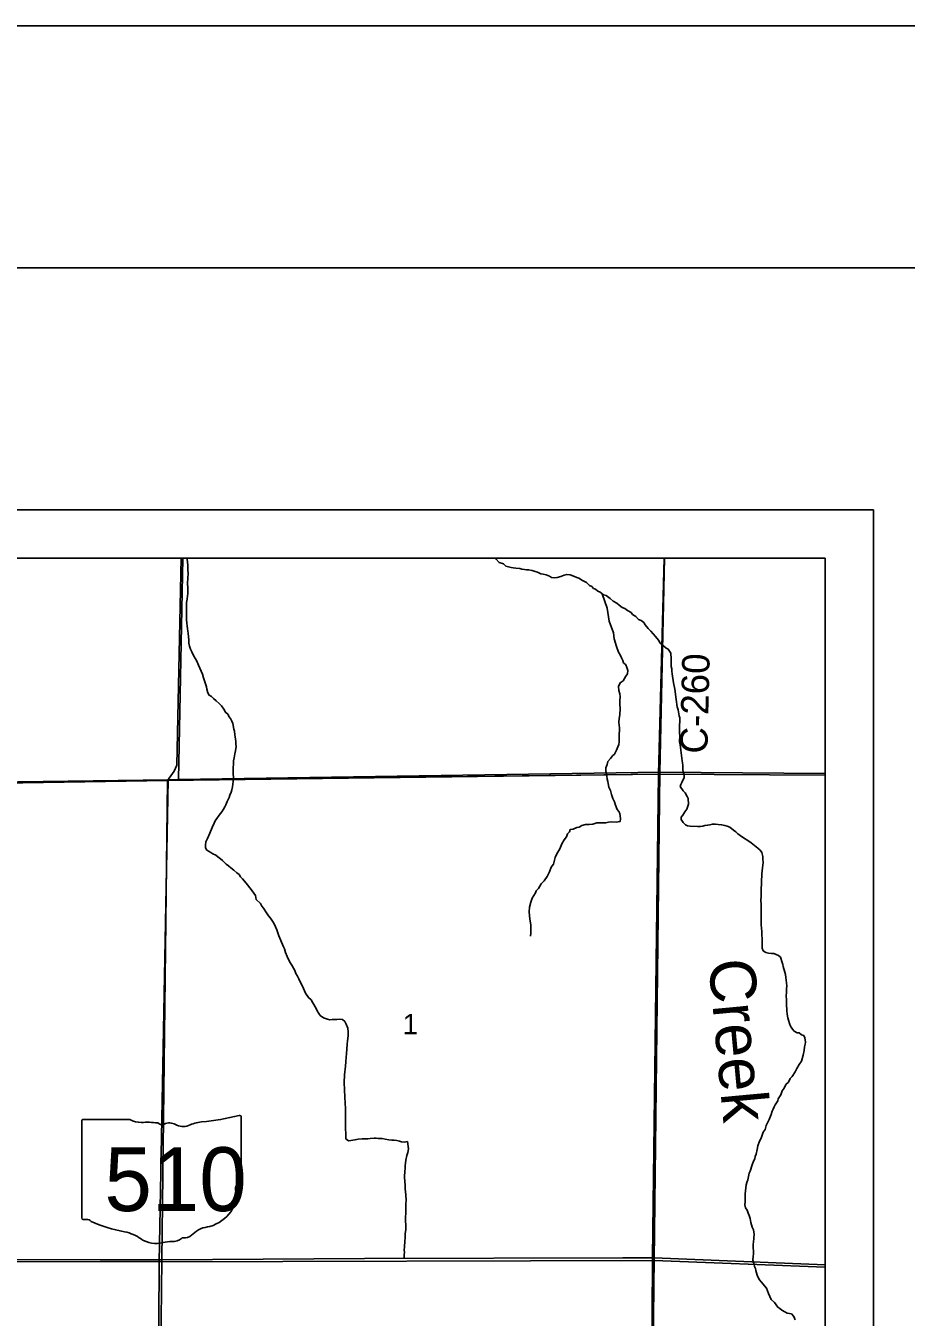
# Model space of a CAD drawing. Extents: x 0 to 34, y 0 to 22.
# Drawn here: x 7.249 to 9.068, y 19.332 to 22 of the extents above; entities that cross this region are included whole.
import ezdxf

# ---------------------------------------------------------------- set-up
doc = ezdxf.new("R2010")
doc.units = 0
for name, color, linetype in [('Default', 7, 'Continuous'), ('GM_X_County_Road', 7, 'Continuous'), ('GM_X_County_Road_Text', 7, 'Continuous'), ('GM_X_Minor_River', 7, 'Continuous'), ('GM_X_Minor_River_Text', 7, 'Continuous'), ('GM_X_Section', 7, 'Continuous'), ('GM_X_Section_Text', 7, 'Continuous'), ('GM_X_State_Location', 7, 'Continuous'), ('GM_X_State_Route', 7, 'Continuous'), ('GM_X_State_Shield', 7, 'Continuous'), ('GM_X_Township', 7, 'Continuous'), ('GM_X_Township_Road', 7, 'Continuous'), ('SH_Border', 7, 'Continuous'), ('SH_Cut_Line', 7, 'Continuous'), ('SH_Data', 7, 'Continuous')]:
    doc.layers.add(name, color=color, linetype=linetype)

msp = doc.modelspace()

# ---------------------------------------------------------------- linework, layer by layer
at = {"layer": 'Default'}
for points in [[(7.573, 20.9), (6.5742, 20.9), (6.5611, 20.4294), (7.5428, 20.4426), (7.5641, 20.4428)], [(8.5686, 20.9), (7.573, 20.9), (7.5641, 20.4428), (8.5583, 20.4582)], [(8.9, 20.4555), (8.9, 20.9), (8.5686, 20.9), (8.5583, 20.4582)], [(8.9, 19.4359), (8.9, 20.4555), (8.5583, 20.4582), (8.547, 19.4493)], [(8.9, 18.4355), (8.9, 19.4359), (8.547, 19.4493), (8.532, 18.4506)]]:
    msp.add_lwpolyline(points, close=True, dxfattribs=at)
at = {"layer": 'GM_X_County_Road'}
msp.add_line((8.5562, 20.4539), (8.5678, 20.9), dxfattribs=at)
msp.add_lwpolyline([(6.5577, 20.4253), (7.5411, 20.4409), (8.5562, 20.4539)], dxfattribs=at)
at = {"layer": 'GM_X_Minor_River'}
for points in [[(7.5819, 20.9), (7.582, 20.8985), (7.5824, 20.8917), (7.5832, 20.886), (7.5836, 20.878), (7.5837, 20.8666), (7.5833, 20.8609), (7.583, 20.8564), (7.5826, 20.851)], [(8.2191, 20.9), (8.2205, 20.8985), (8.2266, 20.8913), (8.2353, 20.8883), (8.2407, 20.8838), (8.2456, 20.8827), (8.2513, 20.8812), (8.2559, 20.8801), (8.2612, 20.8793), (8.2696, 20.879), (8.2737, 20.8779), (8.2787, 20.8772), (8.2829, 20.8764), (8.2874, 20.8764), (8.2946, 20.8749), (8.3011, 20.8727), (8.3057, 20.8712), (8.3129, 20.8682), (8.3174, 20.8675), (8.3239, 20.866), (8.3307, 20.863), (8.3349, 20.8607), (8.341, 20.8596), (8.3463, 20.8604), (8.3543, 20.8627), (8.3611, 20.8654), (8.3664, 20.8669), (8.3732, 20.8658), (8.3786, 20.864), (8.3869, 20.8606), (8.3915, 20.8587), (8.3991, 20.8542), (8.4071, 20.8497), (8.4136, 20.844), (8.4178, 20.8421), (8.4216, 20.8379), (8.4258, 20.8364), (8.4307, 20.8319), (8.4353, 20.83), (8.4425, 20.8248), (8.4475, 20.8229), (8.4559, 20.8172), (8.4623, 20.8116), (8.47, 20.8074), (8.4749, 20.8033), (8.4806, 20.7983), (8.4863, 20.7961), (8.4921, 20.7923), (8.4993, 20.7878), (8.5023, 20.7836), (8.5092, 20.7799), (8.5149, 20.7738), (8.5202, 20.7716), (8.5256, 20.7674), (8.5283, 20.7625), (8.5348, 20.7549), (8.5401, 20.7492), (8.5447, 20.7443), (8.5496, 20.7387), (8.5561, 20.7307), (8.5596, 20.725), (8.5664, 20.7194), (8.5718, 20.7141), (8.576, 20.7122), (8.5817, 20.7042), (8.5818, 20.6921), (8.5818, 20.6852), (8.5822, 20.6765), (8.5834, 20.672), (8.5834, 20.667), (8.5842, 20.6613), (8.5866, 20.6431), (8.5893, 20.6298)], [(7.5826, 20.851), (7.5831, 20.8366), (7.5831, 20.8263), (7.5828, 20.8222), (7.5817, 20.8153), (7.5809, 20.8085), (7.5806, 20.8009), (7.5806, 20.7959), (7.5803, 20.7887), (7.5803, 20.7796), (7.5807, 20.7728), (7.5811, 20.7667), (7.5819, 20.7595), (7.5827, 20.7549), (7.5835, 20.7492), (7.5839, 20.7451), (7.5847, 20.7378), (7.5851, 20.7318), (7.5855, 20.7245), (7.5867, 20.7185), (7.5886, 20.7124), (7.5913, 20.7071), (7.5955, 20.6976), (7.5994, 20.6923), (7.6017, 20.6874), (7.6055, 20.6791), (7.6078, 20.6734), (7.6136, 20.6605), (7.6155, 20.6529), (7.6186, 20.6446), (7.6205, 20.6389), (7.6217, 20.6343), (7.6228, 20.6294), (7.6248, 20.6222), (7.6271, 20.6172), (7.632, 20.6142), (7.6366, 20.6101), (7.6419, 20.6055), (7.648, 20.6002), (7.6526, 20.595), (7.6576, 20.5885), (7.661, 20.5821), (7.6664, 20.5775), (7.6683, 20.5734), (7.6717, 20.5692), (7.674, 20.5639), (7.676, 20.559), (7.6787, 20.5468), (7.6794, 20.5427), (7.6806, 20.5354), (7.6814, 20.5313), (7.6822, 20.5214), (7.6826, 20.5161), (7.683, 20.5111), (7.6819, 20.502), (7.6804, 20.4959), (7.679, 20.4876), (7.6779, 20.4815), (7.6779, 20.4762), (7.6772, 20.4663), (7.6772, 20.4534), (7.6776, 20.4484), (7.6773, 20.4386), (7.6766, 20.4332), (7.6755, 20.4279), (7.674, 20.4215), (7.6729, 20.4169), (7.6702, 20.4108), (7.6684, 20.4062), (7.6669, 20.4017), (7.6646, 20.3975), (7.662, 20.391), (7.6597, 20.3864), (7.6567, 20.3819), (7.6537, 20.3765), (7.6484, 20.3693), (7.6432, 20.3624), (7.6398, 20.3575), (7.6375, 20.3529), (7.6334, 20.3438), (7.6285, 20.332), (7.624, 20.3209), (7.6202, 20.3141), (7.6195, 20.3072), (7.6195, 20.3023), (7.6218, 20.2977), (7.626, 20.2951), (7.6306, 20.2925), (7.6348, 20.2898), (7.6409, 20.2868), (7.6451, 20.283), (7.6508, 20.2793), (7.655, 20.2755), (7.6626, 20.2683), (7.6672, 20.2645), (7.6721, 20.2604), (7.6782, 20.2555), (7.6847, 20.2502), (7.6893, 20.2468), (7.692, 20.2422), (7.6965, 20.2381)], [(8.4396, 20.8269), (8.4499, 20.7971), (8.4542, 20.7701), (8.4631, 20.7462), (8.4643, 20.7337), (8.4693, 20.7181), (8.4731, 20.7064), (8.4769, 20.7007), (8.4796, 20.6943), (8.4823, 20.6886), (8.4839, 20.6844), (8.4884, 20.6802), (8.4904, 20.6742), (8.4927, 20.6685), (8.4919, 20.6613), (8.4882, 20.6567), (8.4829, 20.6472), (8.4769, 20.643), (8.4731, 20.6353), (8.4739, 20.6266), (8.4758, 20.6202), (8.477, 20.6148), (8.4763, 20.6057), (8.4763, 20.5989), (8.4767, 20.5898), (8.4761, 20.5769), (8.4746, 20.5689), (8.4739, 20.5616), (8.4746, 20.5544), (8.475, 20.5503), (8.4755, 20.5442), (8.4747, 20.537), (8.4744, 20.5309), (8.4744, 20.5206), (8.4737, 20.5153), (8.4722, 20.5104), (8.4688, 20.5039), (8.4651, 20.4955), (8.4605, 20.4917), (8.4568, 20.4867), (8.4515, 20.4806), (8.4496, 20.4738), (8.447, 20.4669), (8.447, 20.4597), (8.4486, 20.4548), (8.4494, 20.4506), (8.4501, 20.4438), (8.4513, 20.4388), (8.4521, 20.4347), (8.4536, 20.4271), (8.4567, 20.4203), (8.4587, 20.4123), (8.4614, 20.4036), (8.4648, 20.3971), (8.4671, 20.3899), (8.4706, 20.3812), (8.474, 20.3767), (8.4759, 20.3725), (8.4767, 20.3679), (8.4775, 20.3615), (8.4768, 20.3565), (8.4684, 20.355), (8.4597, 20.3553), (8.4529, 20.3549), (8.4468, 20.3537), (8.4388, 20.3533), (8.4282, 20.3533), (8.424, 20.3525), (8.4199, 20.3509), (8.4127, 20.3501), (8.4051, 20.3501), (8.3975, 20.3478), (8.3918, 20.3447), (8.3873, 20.3436), (8.3797, 20.3405), (8.3736, 20.3397), (8.3717, 20.3348), (8.368, 20.3306), (8.3661, 20.3245), (8.3612, 20.3184), (8.3563, 20.31), (8.3518, 20.2997), (8.3458, 20.2898), (8.3424, 20.2818), (8.339, 20.2685), (8.3341, 20.262), (8.3308, 20.2525), (8.3259, 20.2426), (8.3195, 20.2335), (8.3131, 20.2277), (8.3104, 20.2228), (8.3078, 20.2182), (8.3033, 20.2133), (8.3014, 20.2091), (8.2984, 20.2037), (8.2946, 20.198), (8.292, 20.19), (8.2894, 20.1794), (8.2883, 20.1695), (8.2891, 20.1623), (8.2899, 20.1547)], [(8.5893, 20.6298), (8.5912, 20.6196), (8.592, 20.6131), (8.5924, 20.6082), (8.5948, 20.593), (8.5967, 20.5869), (8.5987, 20.5748), (8.5998, 20.5706), (8.6002, 20.5653), (8.5995, 20.5528), (8.5992, 20.5474), (8.5992, 20.5417), (8.5997, 20.5307), (8.5993, 20.525), (8.5993, 20.5205), (8.6005, 20.5148), (8.6013, 20.5098), (8.6017, 20.5038), (8.6025, 20.4981), (8.604, 20.4874), (8.6045, 20.4814), (8.6052, 20.4772), (8.606, 20.4723), (8.6064, 20.4677), (8.6064, 20.4628), (8.6076, 20.4571), (8.6092, 20.4521), (8.6088, 20.4464), (8.6062, 20.4419), (8.6039, 20.4369), (8.6017, 20.4327), (8.6009, 20.4285), (8.607, 20.4198), (8.6109, 20.4153), (8.6154, 20.4081), (8.6174, 20.4039), (8.6182, 20.3922), (8.6159, 20.3861), (8.6141, 20.3819), (8.6103, 20.3762), (8.6065, 20.3693), (8.6028, 20.3651), (8.6028, 20.3602), (8.607, 20.3541), (8.6119, 20.3492), (8.6161, 20.3477), (8.6214, 20.347), (8.6363, 20.3463), (8.6427, 20.3463), (8.6473, 20.3467), (8.6514, 20.3479), (8.6575, 20.349), (8.6621, 20.3494), (8.6674, 20.351), (8.6738, 20.351), (8.6795, 20.3503), (8.6863, 20.3496), (8.6928, 20.3481), (8.6977, 20.3469), (8.7035, 20.3443), (8.7107, 20.3383), (8.716, 20.3353), (8.7195, 20.3311), (8.7248, 20.3277), (8.7297, 20.3239), (8.7427, 20.316), (8.7473, 20.3122), (8.7545, 20.307), (8.761, 20.3013), (8.7659, 20.2968), (8.7694, 20.2926), (8.7713, 20.2839), (8.7717, 20.2778), (8.7721, 20.2721), (8.7714, 20.2656), (8.7711, 20.2614), (8.77, 20.2535), (8.7696, 20.2489), (8.7692, 20.244), (8.7689, 20.2348), (8.7686, 20.228), (8.7682, 20.2166), (8.7683, 20.2113), (8.7679, 20.2056), (8.7679, 20.2014), (8.7676, 20.1938), (8.768, 20.1851), (8.7681, 20.1794), (8.7677, 20.1737), (8.7678, 20.1631), (8.7682, 20.1574), (8.7682, 20.1429), (8.769, 20.1357), (8.7691, 20.1289), (8.7695, 20.1209), (8.7699, 20.1156), (8.7703, 20.1087), (8.7703, 20.1038), (8.77, 20.0985), (8.77, 20.0943), (8.7723, 20.089)], [(7.6965, 20.2381), (7.7007, 20.2332), (7.7069, 20.2256), (7.7164, 20.2131), (7.7233, 20.2036), (7.7248, 20.1953), (7.7332, 20.1866), (7.7363, 20.1813), (7.7394, 20.1771), (7.7462, 20.1673), (7.7501, 20.1616), (7.7539, 20.1563), (7.7581, 20.1502), (7.7619, 20.1446), (7.7673, 20.1328), (7.7715, 20.1199), (7.7808, 20.0972), (7.7831, 20.093), (7.7854, 20.0854), (7.7885, 20.0775), (7.7927, 20.0687), (7.7954, 20.0638), (7.798, 20.0596), (7.8015, 20.0532), (7.8042, 20.0483), (7.8068, 20.0422), (7.8099, 20.0365), (7.8126, 20.0312), (7.8149, 20.0263), (7.8203, 20.0164), (7.8245, 20.0062), (7.8264, 20.002), (7.8325, 19.9926), (7.8379, 19.9877), (7.8413, 19.9816), (7.8482, 19.9702), (7.8509, 19.9649), (7.854, 19.96), (7.857, 19.9558), (7.8635, 19.9506), (7.8681, 19.9491), (7.8722, 19.9479), (7.8768, 19.9468), (7.8813, 19.9472), (7.887, 19.9476), (7.8912, 19.9473), (7.8977, 19.9477), (7.903, 19.947), (7.9076, 19.9432), (7.9102, 19.9379), (7.9137, 19.9292), (7.9149, 19.9216), (7.9149, 19.9136), (7.9135, 19.9029), (7.9127, 19.8965), (7.9116, 19.8858), (7.9109, 19.8771), (7.9106, 19.8687), (7.9099, 19.8604), (7.9092, 19.8505), (7.9084, 19.8452), (7.9077, 19.8383), (7.9073, 19.8338), (7.907, 19.8292), (7.9067, 19.8205), (7.9068, 19.7988), (7.9076, 19.7901), (7.908, 19.7833), (7.9084, 19.7779), (7.9084, 19.7726), (7.9088, 19.7658), (7.909, 19.7286), (7.9094, 19.7229), (7.9095, 19.7107), (7.9099, 19.7054), (7.9099, 19.7005), (7.9156, 19.6967), (7.9198, 19.6971), (7.9285, 19.6986), (7.9353, 19.7002), (7.9433, 19.7006), (7.9498, 19.701), (7.9551, 19.7011), (7.96, 19.7015), (7.9684, 19.7019), (7.9725, 19.7019), (7.9767, 19.7015), (7.9847, 19.7012), (7.9911, 19.7001), (7.9984, 19.699), (8.0048, 19.6983), (8.0098, 19.6979), (8.0151, 19.6972), (8.0204, 19.696), (8.0246, 19.6949), (8.0303, 19.6942), (8.0371, 19.695)], [(8.2899, 20.1547), (8.2911, 20.1471), (8.2918, 20.1422), (8.2923, 20.1361), (8.2923, 20.1304), (8.2919, 20.1254), (8.2916, 20.1194)], [(8.7723, 20.089), (8.7776, 20.0856), (8.7833, 20.0845), (8.7894, 20.0838), (8.794, 20.0834), (8.7989, 20.0819), (8.8039, 20.0797), (8.808, 20.0759), (8.8115, 20.0653), (8.8131, 20.0607), (8.8138, 20.0565), (8.8169, 20.0451), (8.8185, 20.0402), (8.8193, 20.0341), (8.8205, 20.0231), (8.8209, 20.0163), (8.8205, 20.0114), (8.8202, 20.0015), (8.8198, 19.9973), (8.8203, 19.9867), (8.8203, 19.9813), (8.8207, 19.9749), (8.8211, 19.97), (8.8211, 19.965), (8.8219, 19.9586), (8.8231, 19.951), (8.8246, 19.9457), (8.8266, 19.9388), (8.8285, 19.9335), (8.8331, 19.9275), (8.8361, 19.9233), (8.8422, 19.9199), (8.8464, 19.9199), (8.8517, 19.9158), (8.8559, 19.9139), (8.8586, 19.9094), (8.8594, 19.9006), (8.8587, 19.8964), (8.8579, 19.8907), (8.8568, 19.8835), (8.855, 19.8736), (8.8513, 19.8615), (8.8464, 19.8546), (8.8415, 19.8462), (8.8381, 19.839), (8.8321, 19.8295), (8.8279, 19.8256), (8.8245, 19.818), (8.8192, 19.8127), (8.8159, 19.8051), (8.8117, 19.8001), (8.8087, 19.7914), (8.8031, 19.7834), (8.8023, 19.7792), (8.797, 19.7708), (8.7952, 19.7666), (8.7925, 19.762), (8.791, 19.7578), (8.7888, 19.751), (8.7843, 19.7407), (8.7817, 19.735), (8.7787, 19.7282), (8.7764, 19.7198), (8.7723, 19.7148), (8.7682, 19.7023), (8.7644, 19.6962), (8.7614, 19.6863), (8.7595, 19.6787), (8.7577, 19.6692), (8.7558, 19.6646), (8.7547, 19.6593), (8.7525, 19.6543), (8.7495, 19.6471), (8.745, 19.6342), (8.7431, 19.63), (8.7405, 19.6163), (8.7382, 19.6106), (8.7371, 19.606), (8.7357, 19.5931), (8.7349, 19.5874), (8.735, 19.5794), (8.7347, 19.5703), (8.7343, 19.5646), (8.7358, 19.5585), (8.7393, 19.5532), (8.7412, 19.5472), (8.7435, 19.5422), (8.7455, 19.5362), (8.7466, 19.5278), (8.7493, 19.5183), (8.752, 19.5127), (8.7532, 19.5081), (8.7536, 19.5035), (8.7525, 19.4876), (8.7514, 19.483), (8.7515, 19.4747), (8.7519, 19.4694), (8.7519, 19.4629), (8.7515, 19.458), (8.7508, 19.4504), (8.752, 19.4458)], [(8.0371, 19.695), (8.0395, 19.6798), (8.038, 19.6726), (8.0357, 19.6661), (8.0335, 19.657), (8.0324, 19.6452), (8.0321, 19.6391), (8.0317, 19.6346), (8.031, 19.6216), (8.0322, 19.6046), (8.0327, 19.5966), (8.0331, 19.592), (8.0339, 19.5844), (8.0343, 19.5742), (8.034, 19.5658), (8.034, 19.5609), (8.0336, 19.5533), (8.0337, 19.5457), (8.0333, 19.5404), (8.0335, 19.5138), (8.0324, 19.5043), (8.0324, 19.4955), (8.0317, 19.4898), (8.031, 19.4769), (8.0306, 19.4716), (8.0307, 19.4663), (8.0303, 19.4617), (8.0303, 19.4556)], [(8.752, 19.4458), (8.7535, 19.4413), (8.7543, 19.4371), (8.7562, 19.4329), (8.757, 19.4287), (8.7582, 19.4238), (8.7601, 19.4189), (8.7639, 19.4105), (8.7685, 19.4049), (8.775, 19.3969), (8.7792, 19.3924), (8.7834, 19.381), (8.7888, 19.3689), (8.7953, 19.3624), (8.8022, 19.353), (8.8067, 19.35), (8.8109, 19.3469), (8.817, 19.3432), (8.822, 19.3409), (8.8265, 19.3402), (8.8307, 19.3391), (8.8357, 19.3338), (8.8384, 19.3266)]]:
    msp.add_lwpolyline(points, dxfattribs=at)
at = {"layer": 'GM_X_Section'}
for points in [[(7.5428, 20.4426), (7.5241, 19.4466), (6.5246, 19.4487), (6.5354, 20.4284), (6.5611, 20.4294)], [(7.5641, 20.4428), (8.5583, 20.4582), (8.547, 19.4493), (7.5241, 19.4466), (7.5428, 20.4426)], [(6.5246, 19.4487), (7.5241, 19.4466), (7.5189, 18.4589), (6.5078, 18.4687)], [(7.5241, 19.4466), (8.547, 19.4493), (8.532, 18.4506), (7.5189, 18.4589)]]:
    msp.add_lwpolyline(points, close=True, dxfattribs=at)
at = {"layer": 'GM_X_State_Route'}
msp.add_line((7.5295, 19.4511), (7.5411, 20.4409), dxfattribs=at)
for points in [[(7.5411, 20.4409), (7.5551, 20.4601), (7.5609, 20.4726), (7.5693, 20.9)], [(7.5243, 18.7703), (7.5244, 18.7991), (7.525, 18.8586), (7.5253, 18.9271), (7.5258, 19.0141), (7.5265, 19.1008), (7.5267, 19.2058), (7.528, 19.327), (7.5295, 19.4511)]]:
    msp.add_lwpolyline(points, dxfattribs=at)
at = {"layer": 'GM_X_State_Shield'}
for p, q in [((7.4637, 19.7409), (7.3672, 19.7409)), ((7.6936, 19.6412), (7.6936, 19.7459)), ((7.364, 19.7375), (7.364, 19.5374)), ((7.6935, 19.6412), (7.6936, 19.6412))]:
    msp.add_line(p, q, dxfattribs=at)
for centre, major_axis, start_param, end_param in [((7.3678, 19.7379), (0.00382, 0), 1.712693, 3.28349), ((7.4867, 19.7642), (0.037, 0), 4.042523, 4.731795), ((7.5762, 20.0138), (0.3495, 0), 4.814394, 5.042369), ((7.6899, 19.7463), (0.00367, 0), 6.141152, 7.989035), ((7.499, 19.6286), (0.133, 0), 1.404758, 1.657858), ((7.5292, 19.739), (0.0107, 0), 3.836095, 5.185415), ((7.5449, 19.7158), (0.0222, 0), 0.950623, 2.079405), ((7.5736, 19.7475), (0.0267, 0), 4.081561, 5.145723), ((7.6207, 19.6798), (0.0703, 0), 1.699011, 2.107814), ((7.6927, 19.6335), (0.00568, 0), 1.883978, 3.671073), ((7.6897, 19.6408), (0.00393, 0), 5.05454, 6.418171), ((7.7067, 19.5974), (0.0248, 0), 2.387724, 3.262537), ((7.6566, 19.6203), (0.0341, 0), 5.934695, 6.695948), ((7.5957, 19.5841), (0.0874, 0), 5.101752, 6.440018), ((7.3678, 19.5369), (0.00385, 0), 3.00124, 4.508301), ((7.3684, 19.5574), (0.0294, 0), 4.665946, 4.897461), ((7.3744, 19.5258), (0.0106, 0), 0.519207, 1.627899), ((7.5082, 19.7056), (0.2524, 0), 4.195997, 4.488961), ((7.433, 19.4475), (0.079, 0), 0.823519, 1.323587), ((7.5719, 19.518), (0.0282, 0), 4.937069, 5.64225), ((7.6326, 19.4812), (0.0479, 0), 1.647645, 2.488434), ((7.5184, 19.5248), (0.0501, 0), 4.026481, 4.996735), ((7.5473, 19.4556), (0.0412, 0), 1.495662, 1.94098), ((7.551, 19.5098), (0.0267, 0), 4.691044, 5.507374), ((7.5751, 19.4905), (0.00752, 0), 1.147584, 2.315152)]:
    msp.add_ellipse(centre, major_axis=major_axis, ratio=0.8, start_param=start_param, end_param=end_param, dxfattribs=at)
at = {"layer": 'GM_X_Township'}
msp.add_lwpolyline([(4.5784, 20.3968), (5.284, 20.4086), (5.325, 20.4092), (6.5316, 20.4254), (6.5575, 20.4259), (7.5409, 20.4415), (8.556, 20.4544), (8.5437, 19.4556), (8.5436, 19.4447), (8.5388, 18.7451), (8.5216, 17.7888), (8.5215, 17.7806), (8.5214, 17.7731), (8.5094, 16.832), (8.5093, 16.83), (8.4947, 15.4259), (8.4895, 15.0042)], dxfattribs=at)
at = {"layer": 'GM_X_Township_Road'}
for p, q in [((8.5466, 19.4551), (8.5562, 20.4539)), ((8.539, 18.7445), (8.5466, 19.4551)), ((8.5466, 19.4551), (8.9, 19.4405))]:
    msp.add_line(p, q, dxfattribs=at)
for points in [[(4.5784, 20.3968), (5.284, 20.4086), (5.325, 20.4092), (6.5316, 20.4254), (6.5575, 20.4259), (7.5409, 20.4415), (8.556, 20.4544), (8.5676, 20.9), (2.6262, 20.9)], [(6.7761, 19.4529), (6.939, 19.4523), (7.4021, 19.4507), (7.5295, 19.4511)], [(7.5295, 19.4511), (7.9485, 19.4539), (8.482, 19.4546), (8.5439, 19.4551), (8.5466, 19.4551)]]:
    msp.add_lwpolyline(points, dxfattribs=at)
for points in [[(8.9, 20.4518), (8.9, 20.9), (8.5676, 20.9), (8.556, 20.4544)], [(8.9, 14.4215), (8.9, 20.4518), (8.556, 20.4544), (8.5437, 19.4556), (8.5436, 19.4447), (8.5388, 18.7451), (8.5216, 17.7888), (8.5215, 17.7806), (8.5214, 17.7731), (8.5094, 16.832), (8.5093, 16.83), (8.4947, 15.4259), (8.4895, 15.0042), (8.4811, 14.4273), (8.4833, 14.4273), (8.6169, 14.4256), (8.6362, 14.4253), (8.7095, 14.4242), (8.7648, 14.4233), (8.8009, 14.4228), (8.8456, 14.4221)]]:
    msp.add_lwpolyline(points, close=True, dxfattribs=at)
at = {"layer": 'SH_Border'}
msp.add_lwpolyline([(1.5, 21.5), (33.5, 21.5), (33.5, 0.5), (1.5, 0.5)], close=True, dxfattribs=at)
at = {"layer": 'SH_Cut_Line'}
msp.add_lwpolyline([(0, 0), (34, 0), (34, 22), (0, 22)], close=True, dxfattribs=at)
msp.add_lwpolyline([(8.9, 14.4215), (8.9, 20.9), (2.1, 20.9)], dxfattribs=at)
at = {"layer": 'SH_Data'}
for p, q in [((2, 21), (9, 21)), ((9, 21), (9, 14)), ((2.1, 20.9), (8.9, 20.9)), ((8.9, 20.9), (8.9, 14.1))]:
    msp.add_line(p, q, dxfattribs=at)

# ---------------------------------------------------------------- texts
at = {"layer": 'GM_X_County_Road_Text'}
msp.add_text('C-260', height=0.05682, rotation=88.6227, dxfattribs=at).set_placement((8.6569, 20.496))
at = {"layer": 'GM_X_Minor_River_Text'}
msp.add_text('Creek', height=0.09475, rotation=275.2949, dxfattribs=at).set_placement((8.6589, 20.0688))
at = {"layer": 'GM_X_Section_Text'}
msp.add_text('1', height=0.0419, rotation=0, dxfattribs=at).set_placement((8.0274, 19.9168))
at = {"layer": 'GM_X_State_Location'}
msp.add_text('510', height=0.000189, rotation=0, dxfattribs=at).set_placement((7.4582, 19.6103))
for s in ['s', 'r']:
    msp.add_text(s, height=0.000189, dxfattribs=at).set_placement((7.5251, 19.6241))
at = {"layer": 'GM_X_State_Shield'}
msp.add_text('510', height=0.13184, dxfattribs=at).set_placement((7.4109, 19.5515))

doc.saveas('drawing.dxf')
